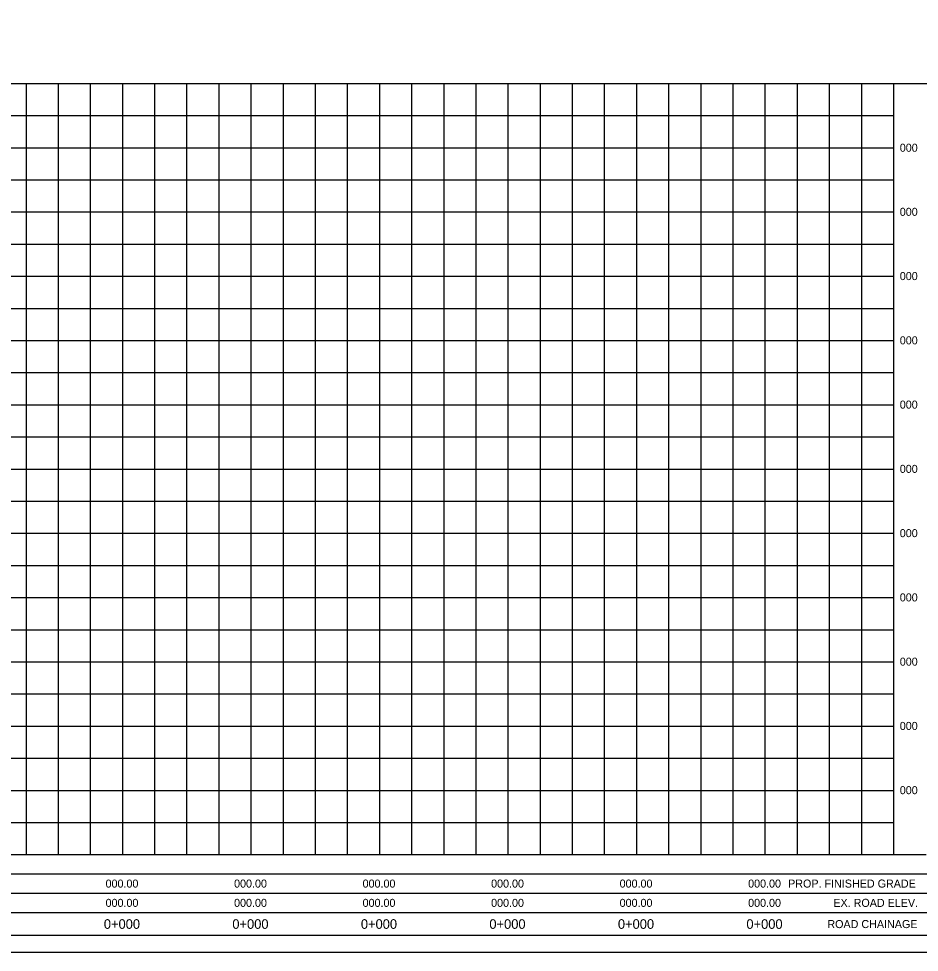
# Model space of a CAD drawing. Extents: x 613360 to 613780, y 4825621 to 4825911.
# Drawn here: x 613569.5 to 613709.7, y 4825620.9 to 4825766.2 of the extents above; entities that cross this region are included whole.
import ezdxf

# ---------------------------------------------------------------- set-up
doc = ezdxf.new("R2010")
doc.units = 0
for name, color, linetype in [('G-ANNO-TEXT', 7, 'Continuous'), ('G-GRID-MAJ', 7, 'Continuous'), ('G-GRID-MIN', 7, 'Continuous'), ('G-TTLB-OTLN', 7, 'Continuous'), ('G-TTLB-OTLN-PB', 7, 'Continuous')]:
    doc.layers.add(name, color=color, linetype=linetype)

msp = doc.modelspace()

# ---------------------------------------------------------------- linework, layer by layer
at = {"layer": 'G-GRID-MAJ'}
for p, q in [((613585.73, 4825636.11), (613585.73, 4825756.11)), ((613605.73, 4825636.11), (613605.73, 4825756.11)), ((613625.73, 4825636.11), (613625.73, 4825756.11)), ((613645.73, 4825636.11), (613645.73, 4825756.11)), ((613665.73, 4825636.11), (613665.73, 4825756.11)), ((613685.73, 4825636.11), (613685.73, 4825756.11)), ((613705.73, 4825636.11), (613705.73, 4825756.11)), ((613385.73, 4825746.11), (613705.73, 4825746.11)), ((613385.73, 4825736.11), (613705.73, 4825736.11)), ((613385.73, 4825726.11), (613705.73, 4825726.11)), ((613385.73, 4825716.11), (613705.73, 4825716.11)), ((613385.73, 4825706.11), (613705.73, 4825706.11)), ((613385.73, 4825696.11), (613705.73, 4825696.11)), ((613385.73, 4825686.11), (613705.73, 4825686.11)), ((613385.73, 4825676.11), (613705.73, 4825676.11)), ((613385.73, 4825666.11), (613705.73, 4825666.11)), ((613385.73, 4825656.11), (613705.73, 4825656.11)), ((613385.73, 4825646.11), (613705.73, 4825646.11))]:
    msp.add_line(p, q, dxfattribs=at)
at = {"layer": 'G-GRID-MIN'}
for p, q in [((613570.73, 4825636.11), (613570.73, 4825756.11)), ((613575.73, 4825636.11), (613575.73, 4825756.11)), ((613580.73, 4825636.11), (613580.73, 4825756.11)), ((613590.73, 4825636.11), (613590.73, 4825756.11)), ((613595.73, 4825636.11), (613595.73, 4825756.11)), ((613600.73, 4825636.11), (613600.73, 4825756.11)), ((613610.73, 4825636.11), (613610.73, 4825756.11)), ((613615.73, 4825636.11), (613615.73, 4825756.11)), ((613620.73, 4825636.11), (613620.73, 4825756.11)), ((613630.73, 4825636.11), (613630.73, 4825756.11)), ((613635.73, 4825636.11), (613635.73, 4825756.11)), ((613640.73, 4825636.11), (613640.73, 4825756.11)), ((613650.73, 4825636.11), (613650.73, 4825756.11)), ((613655.73, 4825636.11), (613655.73, 4825756.11)), ((613660.73, 4825636.11), (613660.73, 4825756.11)), ((613670.73, 4825636.11), (613670.73, 4825756.11)), ((613675.73, 4825636.11), (613675.73, 4825756.11)), ((613680.73, 4825636.11), (613680.73, 4825756.11)), ((613690.73, 4825636.11), (613690.73, 4825756.11)), ((613695.73, 4825636.11), (613695.73, 4825756.11)), ((613700.73, 4825636.11), (613700.73, 4825756.11)), ((613385.73, 4825751.11), (613705.73, 4825751.11)), ((613385.73, 4825741.11), (613705.73, 4825741.11)), ((613385.73, 4825731.11), (613705.73, 4825731.11)), ((613385.73, 4825721.11), (613705.73, 4825721.11)), ((613385.73, 4825711.11), (613705.73, 4825711.11)), ((613385.73, 4825701.11), (613705.73, 4825701.11)), ((613385.73, 4825691.11), (613705.73, 4825691.11)), ((613385.73, 4825681.11), (613705.73, 4825681.11)), ((613385.73, 4825671.11), (613705.73, 4825671.11)), ((613385.73, 4825661.11), (613705.73, 4825661.11)), ((613385.73, 4825651.11), (613705.73, 4825651.11)), ((613385.73, 4825641.11), (613705.73, 4825641.11))]:
    msp.add_line(p, q, dxfattribs=at)
at = {"layer": 'G-TTLB-OTLN'}
for p, q in [((613380.09, 4825756.11), (613774.18, 4825756.11)), ((613380.09, 4825636.11), (613710.78, 4825636.11)), ((613380.09, 4825633.11), (613774.18, 4825633.11)), ((613380.09, 4825630.11), (613749.42, 4825630.11)), ((613380.09, 4825627.11), (613749.42, 4825627.11))]:
    msp.add_line(p, q, dxfattribs=at)
msp.add_lwpolyline([(613380.09, 4825892.08), (613774.18, 4825892.08), (613774.18, 4825623.51), (613380.09, 4825623.51)], close=True, dxfattribs=at)
at = {"layer": 'G-TTLB-OTLN-PB'}
msp.add_lwpolyline([(613359.58, 4825620.91), (613780.27, 4825620.91), (613780.27, 4825894.68), (613359.58, 4825894.68)], close=True, dxfattribs=at)

# ---------------------------------------------------------------- texts
at = {"layer": 'G-ANNO-TEXT'}
for s, height, p in [('000', 1.25, (613706.66, 4825745.48)), ('000.00', 1.25, (613583.06, 4825630.98)), ('000.00', 1.25, (613603.06, 4825630.98)), ('000.00', 1.25, (613623.06, 4825630.98)), ('000.00', 1.25, (613643.06, 4825630.98)), ('000.00', 1.25, (613663.06, 4825630.98)), ('000.00', 1.25, (613683.06, 4825630.98)), ('PROP. FINISHED GRADE', 1.25, (613689.28, 4825630.98)), ('000.00', 1.25, (613583.06, 4825627.98)), ('000.00', 1.25, (613603.06, 4825627.98)), ('000.00', 1.25, (613623.06, 4825627.98)), ('000.00', 1.25, (613643.06, 4825627.98)), ('000.00', 1.25, (613663.06, 4825627.98)), ('000.00', 1.25, (613683.06, 4825627.98)), ('EX. ROAD ELEV.', 1.25, (613696.32, 4825627.98)), ('0+000', 1.5, (613582.79, 4825624.56)), ('0+000', 1.5, (613602.79, 4825624.56)), ('0+000', 1.5, (613622.79, 4825624.56)), ('0+000', 1.5, (613642.79, 4825624.56)), ('0+000', 1.5, (613662.79, 4825624.56)), ('0+000', 1.5, (613682.79, 4825624.56)), ('ROAD CHAINAGE', 1.25, (613695.39, 4825624.68))]:
    msp.add_text(s, height=height, dxfattribs=at).set_placement(p)
for p in [(613706.66, 4825735.51), (613706.66, 4825725.51), (613706.66, 4825715.51), (613706.66, 4825705.51), (613706.66, 4825695.51), (613706.66, 4825685.51), (613706.66, 4825675.51), (613706.66, 4825665.51), (613706.66, 4825655.51), (613706.66, 4825645.51)]:
    msp.add_text('000', height=1.25, rotation=360, dxfattribs=at).set_placement(p)

doc.saveas('drawing.dxf')
